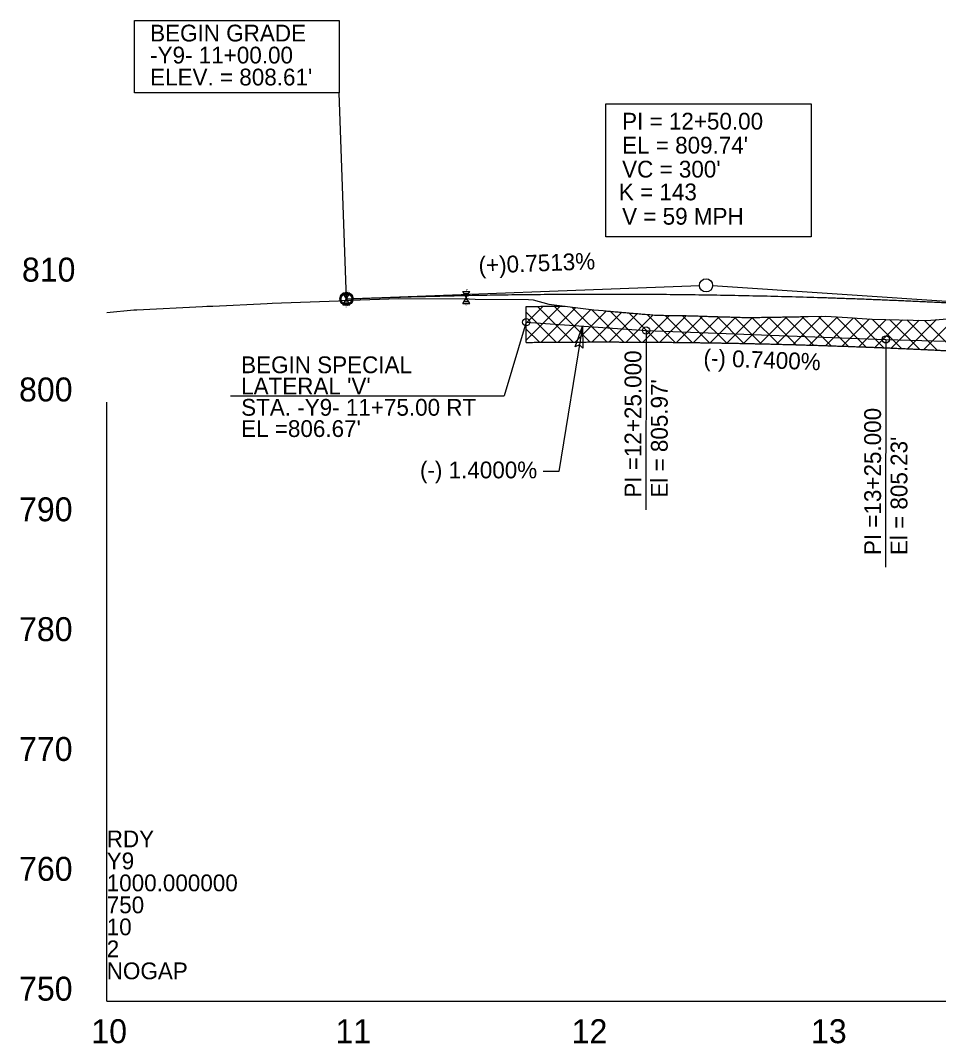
# Model space of a CAD drawing. Extents: x 579185 to 595036, y -53221 to -44640.
# Drawn here: x 591153 to 591536, y -49552.8 to -49125.9 of the extents above; entities that cross this region are included whole.
import ezdxf

# ---------------------------------------------------------------- set-up
doc = ezdxf.new("R2010")
doc.units = 0
for name, color, linetype in [('Exist Profile Cell', 7, 'Continuous'), ('Exist Vertical Profile Ground Line', 7, 'Continuous'), ('Exist Vertical Profile Horizontal Axis Label Major', 7, 'Continuous'), ('Exist Vertical Profile Vertical Axis Label', 7, 'Continuous'), ('Old_Level_2', 7, 'Continuous'), ('Prop Grid Mask', 7, 'Continuous'), ('Prop Hatching', 7, 'Continuous'), ('Prop Terminator CELL', 7, 'Continuous'), ('Prop Vertical Profile Curve Label', 7, 'Continuous'), ('Prop Vertical Profile Ditch Grade Right', 7, 'Continuous'), ('Prop Vertical Profile Ditch Grade Right Label', 7, 'Continuous'), ('Prop Vertical Profile Grade', 7, 'Continuous'), ('Prop Vertical Profile Grade Label', 7, 'Continuous'), ('Prop VPI Ditch Grade Right Label', 7, 'Continuous'), ('Prop VPI Label', 7, 'Continuous')]:
    doc.layers.add(name, color=color, linetype=linetype)

msp = doc.modelspace()

# ---------------------------------------------------------------- linework, layer by layer
at = {"layer": 'Exist Profile Cell'}
for q in [(591188.99, -49285.12), (592048.25, -49535.12), (591188.99, -49535.12)]:
    msp.add_line((591188.99, -49535.12), q, dxfattribs=at)
at = {"layer": 'Exist Vertical Profile Ground Line'}
for points in [[(591188.99, -49247.72), (591200.32, -49246.71), (591201.16, -49246.62), (591201.57, -49246.59), (591228.98, -49245.24), (591230.68, -49245.18), (591233.2, -49245.1), (591255.88, -49243.99), (591258.01, -49243.89), (591285.71, -49242.84), (591286.79, -49242.8), (591310.73, -49241.9), (591340.21, -49242.1), (591342.73, -49242.18), (591364.92, -49242.38), (591366.89, -49242.47), (591373.45, -49244.24), (591392.23, -49246.61), (591396.04, -49246.96), (591396.67, -49247.02), (591397.3, -49247.07), (591397.93, -49247.13), (591398.56, -49247.19), (591399.19, -49247.24), (591399.82, -49247.3), (591400.45, -49247.36), (591401.08, -49247.41), (591401.7, -49247.47), (591402.33, -49247.53), (591402.96, -49247.58), (591403.59, -49247.64), (591404.22, -49247.69), (591404.85, -49247.75), (591405.48, -49247.8), (591406.11, -49247.86), (591406.74, -49247.91), (591407.37, -49247.97), (591408, -49248.02), (591408.63, -49248.07), (591409.25, -49248.13), (591409.88, -49248.18), (591410.51, -49248.23), (591411.14, -49248.29), (591411.77, -49248.34), (591412.4, -49248.39), (591413.03, -49248.44), (591413.66, -49248.49), (591414.29, -49248.55), (591414.92, -49248.6), (591415.55, -49248.65), (591416.18, -49248.7), (591416.8, -49248.75), (591417.43, -49248.8), (591418.06, -49248.85), (591418.69, -49248.88), (591419.32, -49248.89), (591419.95, -49248.91), (591420.58, -49248.92), (591421.21, -49248.93), (591421.84, -49248.94), (591422.47, -49248.95), (591423.1, -49248.96), (591423.73, -49248.97), (591424.35, -49248.98), (591424.98, -49248.99), (591425.61, -49249), (591426.24, -49249.01), (591426.87, -49249.02), (591427.5, -49249.03), (591428.13, -49249.04), (591428.76, -49249.05), (591429.39, -49249.06), (591430.02, -49249.06), (591430.65, -49249.07), (591431.28, -49249.08), (591431.9, -49249.09), (591432.53, -49249.1), (591433.16, -49249.11), (591433.79, -49249.13), (591434.42, -49249.15), (591435.05, -49249.18), (591435.68, -49249.2), (591436.31, -49249.22), (591436.94, -49249.25), (591437.57, -49249.27), (591438.2, -49249.29), (591438.83, -49249.31), (591439.45, -49249.34), (591440.08, -49249.36), (591440.71, -49249.38), (591441.34, -49249.4), (591441.97, -49249.42), (591442.6, -49249.44), (591443.23, -49249.46), (591443.86, -49249.48), (591444.49, -49249.5), (591445.12, -49249.52), (591445.75, -49249.53), (591446.38, -49249.55), (591447, -49249.57), (591447.63, -49249.59)], [(591447.63, -49249.59), (591448.26, -49249.61), (591448.89, -49249.62), (591449.52, -49249.64), (591450.15, -49249.65), (591450.78, -49249.67), (591451.41, -49249.69), (591452.04, -49249.7), (591452.67, -49249.72), (591453.3, -49249.75), (591453.93, -49249.78), (591454.55, -49249.82), (591455.18, -49249.85), (591455.81, -49249.87), (591456.44, -49249.86), (591457.07, -49249.85), (591457.7, -49249.84), (591458.33, -49249.83), (591458.96, -49249.82), (591459.59, -49249.81), (591460.22, -49249.8), (591460.85, -49249.79), (591461.48, -49249.78), (591462.1, -49249.77), (591462.73, -49249.76), (591463.36, -49249.75), (591463.99, -49249.74), (591464.62, -49249.73), (591465.25, -49249.72), (591465.88, -49249.71), (591466.51, -49249.7), (591467.14, -49249.69), (591467.77, -49249.68), (591468.4, -49249.67), (591469.03, -49249.66), (591469.66, -49249.65), (591470.28, -49249.64), (591470.91, -49249.63), (591471.54, -49249.62), (591472.17, -49249.61), (591472.8, -49249.59), (591473.43, -49249.58), (591474.06, -49249.57), (591474.69, -49249.56), (591475.32, -49249.55), (591475.95, -49249.54), (591476.58, -49249.53), (591477.21, -49249.52), (591477.83, -49249.5), (591478.46, -49249.49), (591479.09, -49249.48), (591479.72, -49249.47), (591480.35, -49249.46), (591480.98, -49249.45), (591481.61, -49249.44), (591488.92, -49249.3), (591497.96, -49249.87), (591508.21, -49250.47), (591531.14, -49251.08), (591560.27, -49248.66)]]:
    msp.add_lwpolyline(points, dxfattribs=at)
at = {"layer": 'Old_Level_2'}
for p, q in [((591288.99, -49242.07), (591287.55, -49239.57)), ((591287.55, -49239.57), (591290.43, -49239.57)), ((591288.03, -49240.4), (591289.95, -49240.4)), ((591288.51, -49241.24), (591289.47, -49241.24)), ((591288.99, -49242.07), (591290.43, -49239.57)), ((591338.99, -49241.47), (591337.55, -49238.97)), ((591337.55, -49238.97), (591340.43, -49238.97)), ((591338.03, -49239.8), (591339.95, -49239.8)), ((591338.51, -49240.63), (591339.47, -49240.63)), ((591338.99, -49241.47), (591340.43, -49238.97)), ((591287.55, -49244.57), (591288.99, -49242.07)), ((591287.55, -49244.57), (591290.43, -49244.57)), ((591288.03, -49243.74), (591289.95, -49243.74)), ((591288.51, -49242.91), (591289.47, -49242.91)), ((591290.43, -49244.57), (591288.99, -49242.07)), ((591337.55, -49243.97), (591338.99, -49241.47)), ((591337.55, -49243.97), (591340.43, -49243.97)), ((591338.03, -49243.13), (591339.95, -49243.13)), ((591338.51, -49242.3), (591339.47, -49242.3)), ((591340.43, -49243.97), (591338.99, -49241.47))]:
    msp.add_line(p, q, dxfattribs=at)
at = {"layer": 'Prop Grid Mask'}
for points in [[(591200.54, -49125.91), (591285.94, -49125.91), (591285.94, -49156.1), (591200.54, -49156.1)], [(591397.23, -49160.74), (591482.79, -49160.74), (591482.79, -49216.13), (591397.23, -49216.13)]]:
    msp.add_lwpolyline(points, close=True, dxfattribs=at)
at = {"layer": 'Prop Hatching'}
for p, q in [((591363.99, -49259.31), (591378.19, -49245.11)), ((591363.99, -49252.24), (591371.06, -49245.17)), ((591363.99, -49260.24), (591363.99, -49245.24)), ((591368.65, -49245.19), (591383.54, -49260.08)), ((591375.66, -49245.13), (591390.59, -49260.06)), ((591383.06, -49245.46), (591397.66, -49260.05)), ((591363.99, -49247.6), (591376.51, -49260.12)), ((591370.2, -49260.17), (591384.71, -49245.66)), ((591377.32, -49260.12), (591390.98, -49246.46)), ((591384.43, -49260.08), (591397.43, -49247.09)), ((591391.15, -49246.48), (591404.74, -49260.07)), ((591391.52, -49260.06), (591403.92, -49247.67)), ((591398.6, -49260.05), (591410.43, -49248.23)), ((591398.97, -49247.22), (591411.84, -49260.1)), ((591405.66, -49260.07), (591416.96, -49248.76)), ((591406.73, -49247.91), (591418.96, -49260.14)), ((591412.69, -49260.1), (591423.82, -49248.97)), ((591414.45, -49248.56), (591426.1, -49260.21)), ((591419.72, -49260.15), (591430.79, -49249.07)), ((591421.9, -49248.94), (591433.25, -49260.29)), ((591426.72, -49260.22), (591437.67, -49249.27)), ((591429.08, -49249.05), (591440.43, -49260.4)), ((591433.71, -49260.3), (591444.51, -49249.5)), ((591436.32, -49249.22), (591447.62, -49260.52)), ((591440.68, -49260.4), (591451.39, -49249.69)), ((591443.64, -49249.47), (591454.83, -49260.66)), ((591447.63, -49260.52), (591458.32, -49249.83)), ((591450.92, -49249.67), (591462.06, -49260.82)), ((591454.57, -49260.65), (591465.5, -49249.72)), ((591458.15, -49249.84), (591469.31, -49260.99)), ((591461.49, -49260.8), (591472.7, -49249.6)), ((591465.11, -49249.73), (591476.57, -49261.19)), ((591468.39, -49260.97), (591479.9, -49249.47)), ((591472.06, -49249.61), (591483.86, -49261.4)), ((591475.28, -49261.15), (591487.1, -49249.34)), ((591479.01, -49249.48), (591491.17, -49261.64)), ((591482.15, -49261.35), (591493.89, -49249.61)), ((591485.95, -49249.36), (591498.49, -49261.89)), ((591493.24, -49249.57), (591505.84, -49262.17)), ((591489.01, -49261.57), (591500.56, -49250.02)), ((591495.85, -49261.8), (591507.23, -49250.42)), ((591500.77, -49250.03), (591513.2, -49262.46)), ((591502.67, -49262.05), (591514.09, -49250.63)), ((591508.29, -49250.48), (591520.59, -49262.78)), ((591509.48, -49262.31), (591520.98, -49250.81)), ((591515.55, -49250.67), (591527.99, -49263.11)), ((591516.27, -49262.59), (591527.87, -49250.99)), ((591522.81, -49250.86), (591535.42, -49263.46)), ((591523.05, -49262.88), (591535.19, -49250.74)), ((591529.81, -49263.19), (591542.9, -49250.1)), ((591530.07, -49251.05), (591542.86, -49263.84)), ((591363.99, -49254.67), (591369.5, -49260.18))]:
    msp.add_line(p, q, dxfattribs=at)
for points in [[(591363.99, -49245.24), (591365.01, -49245.23), (591366.02, -49245.22), (591367.04, -49245.21), (591369.04, -49245.19), (591371.03, -49245.17), (591373.03, -49245.15), (591375.03, -49245.13), (591377.02, -49245.12), (591379.02, -49245.11), (591379.43, -49245.11), (591379.84, -49245.1), (591380.24, -49245.1)], [(591363.99, -49260.24), (591365.06, -49260.23), (591366.13, -49260.21), (591367.19, -49260.2), (591369.18, -49260.18), (591371.17, -49260.17), (591373.15, -49260.15), (591375.14, -49260.13), (591377.12, -49260.12), (591379.11, -49260.11), (591381.1, -49260.09), (591383.08, -49260.08), (591385.07, -49260.08), (591387.05, -49260.07), (591389.04, -49260.06), (591391.03, -49260.06), (591393.01, -49260.06), (591395, -49260.05), (591396.98, -49260.05), (591398.97, -49260.05), (591400.96, -49260.06), (591402.94, -49260.06), (591404.93, -49260.07), (591406.91, -49260.07), (591408.9, -49260.08), (591410.89, -49260.09), (591412.87, -49260.1), (591414.86, -49260.11), (591416.84, -49260.13), (591418.83, -49260.14), (591420.82, -49260.16), (591422.8, -49260.18), (591424.79, -49260.2), (591426.77, -49260.22), (591428.76, -49260.24), (591430.75, -49260.26), (591432.73, -49260.29), (591434.72, -49260.31), (591436.71, -49260.34), (591438.69, -49260.37), (591440.68, -49260.4), (591442.66, -49260.43), (591444.65, -49260.47), (591446.64, -49260.5), (591448.62, -49260.54), (591450.61, -49260.57), (591452.59, -49260.61), (591454.58, -49260.65), (591456.57, -49260.69), (591458.55, -49260.74), (591460.54, -49260.78), (591462.52, -49260.83), (591464.51, -49260.87), (591466.5, -49260.92), (591468.48, -49260.97), (591470.47, -49261.02), (591472.45, -49261.08), (591474.44, -49261.13), (591476.43, -49261.18), (591478.41, -49261.24), (591480.4, -49261.3), (591482.38, -49261.36), (591484.37, -49261.42), (591486.36, -49261.48), (591488.34, -49261.55), (591490.33, -49261.61), (591492.31, -49261.68), (591494.3, -49261.75), (591496.29, -49261.81), (591498.27, -49261.89), (591500.26, -49261.96), (591502.24, -49262.03), (591504.23, -49262.11), (591506.22, -49262.18), (591508.2, -49262.26), (591510.19, -49262.34), (591512.17, -49262.42), (591514.16, -49262.5), (591516.15, -49262.58), (591518.13, -49262.67), (591520.12, -49262.75), (591522.1, -49262.84), (591524.09, -49262.93), (591526.08, -49263.02), (591528.06, -49263.11), (591530.05, -49263.21), (591532.03, -49263.3), (591534.02, -49263.4), (591536.01, -49263.49), (591537.99, -49263.59), (591539.98, -49263.69), (591541.96, -49263.79), (591543.95, -49263.89), (591545.94, -49264), (591547.92, -49264.1), (591549.91, -49264.21), (591551.89, -49264.32), (591553.88, -49264.43), (591555.87, -49264.54), (591557.85, -49264.65), (591559.84, -49264.77), (591561.83, -49264.88), (591563.81, -49265), (591565.8, -49265.12), (591567.78, -49265.24), (591569.77, -49265.36), (591571.76, -49265.48), (591573.74, -49265.6), (591575.73, -49265.73), (591577.23, -49265.82), (591578.74, -49265.92), (591580.24, -49266.02)]]:
    msp.add_open_spline(points, degree=3, dxfattribs=at)
at = {"layer": 'Prop Terminator CELL'}
msp.add_lwpolyline([(591384.47, -49262.04), (591387.46, -49253.41), (591387.58, -49262.6), (591386.18, -49261.21)], close=True, dxfattribs=at)
at = {"layer": 'Prop Vertical Profile Curve Label'}
msp.add_line((591288.99, -49242.07), (591285.94, -49156.1), dxfattribs=at)
msp.add_circle((591288.99, -49242.07), 2.25, dxfattribs=at)
at = {"layer": 'Prop Vertical Profile Ditch Grade Right'}
msp.add_line((591363.99, -49251.77), (591413.99, -49255.27), dxfattribs=at)
msp.add_lwpolyline([(591413.99, -49255.27), (591513.99, -49258.97), (591538.99, -49259.77)], dxfattribs=at)
at = {"layer": 'Prop Vertical Profile Ditch Grade Right Label'}
for p, q in [((591363.99, -49251.77), (591354.74, -49282.54)), ((591387.46, -49253.41), (591377.53, -49314.04)), ((591413.99, -49255.27), (591413.92, -49330.07)), ((591513.99, -49258.97), (591513.9, -49354.04)), ((591240.66, -49282.54), (591354.74, -49282.54)), ((591377.53, -49314.04), (591371.09, -49314.04))]:
    msp.add_line(p, q, dxfattribs=at)
at = {"layer": 'Prop Vertical Profile Grade'}
msp.add_spline([(591288.99, -49242.07), (591294.99, -49241.85), (591300.99, -49241.65), (591306.99, -49241.45), (591312.99, -49241.27), (591318.99, -49241.1), (591324.99, -49240.95), (591330.99, -49240.8), (591336.99, -49240.67), (591342.99, -49240.55), (591348.99, -49240.45), (591354.99, -49240.35), (591360.99, -49240.27), (591366.99, -49240.21), (591372.99, -49240.15), (591378.99, -49240.11), (591384.99, -49240.08), (591390.99, -49240.06), (591396.99, -49240.06), (591402.99, -49240.06), (591408.99, -49240.08), (591414.99, -49240.12), (591420.99, -49240.16), (591426.99, -49240.22), (591432.99, -49240.29), (591438.99, -49240.37), (591444.99, -49240.47), (591450.99, -49240.58), (591456.99, -49240.7), (591462.99, -49240.83), (591468.99, -49240.98), (591474.99, -49241.14), (591480.99, -49241.31), (591486.99, -49241.49), (591492.99, -49241.69), (591498.99, -49241.9), (591504.99, -49242.12), (591510.99, -49242.36), (591516.99, -49242.6), (591522.99, -49242.86), (591528.99, -49243.14), (591534.99, -49243.42), (591540.99, -49243.72), (591546.99, -49244.03), (591552.99, -49244.35), (591558.99, -49244.69), (591564.99, -49245.03), (591570.99, -49245.4), (591576.99, -49245.77), (591582.99, -49246.15), (591588.99, -49246.55)], degree=3, dxfattribs=at)
at = {"layer": 'Prop VPI Ditch Grade Right Label'}
for centre in [(591363.99, -49251.77), (591413.99, -49255.27), (591513.99, -49258.97)]:
    msp.add_circle(centre, 1.5, dxfattribs=at)
at = {"layer": 'Prop VPI Label'}
for p, q in [((591288.99, -49242.07), (591436.24, -49236.54)), ((591588.99, -49246.55), (591441.73, -49236.62))]:
    msp.add_line(p, q, dxfattribs=at)
for centre in [(591438.99, -49236.44), (591288.99, -49242.07)]:
    msp.add_circle(centre, 2.75, dxfattribs=at)

# ---------------------------------------------------------------- texts
at = {"layer": 'Exist Profile Cell'}
for s, p in [('RDY', (591188.99, -49470.88)), ('Y9', (591188.99, -49480.06)), ('1000.000000', (591188.99, -49489.23)), ('750', (591188.99, -49498.41)), ('10', (591188.99, -49507.59)), ('2', (591188.99, -49516.76)), ('NOGAP', (591188.99, -49525.94))]:
    msp.add_text(s, height=7, dxfattribs=at).set_placement(p)
at = {"layer": 'Exist Vertical Profile Horizontal Axis Label Major'}
for s, p in [('10', (591182.57, -49552.62)), ('11', (591284.41, -49552.62)), ('12', (591382.96, -49552.62)), ('13', (591482.8, -49552.62))]:
    msp.add_text(s, height=10, dxfattribs=at).set_placement(p)
at = {"layer": 'Exist Vertical Profile Vertical Axis Label'}
for s, p in [('810', (591153.62, -49234.87)), ('800', (591152.42, -49284.87)), ('790', (591152.42, -49334.87)), ('780', (591152.42, -49384.87)), ('770', (591152.42, -49434.87)), ('760', (591152.42, -49484.87)), ('750', (591152.42, -49534.87))]:
    msp.add_text(s, height=10, dxfattribs=at).set_placement(p)
at = {"layer": 'Old_Level_2'}
for p in [(591288.76, -49239.41), (591338.76, -49238.81), (591288.56, -49245.58), (591338.56, -49244.97)]:
    msp.add_text('6"', height=0.8, dxfattribs=at).set_placement(p)
at = {"layer": 'Prop Vertical Profile Curve Label'}
for s, p in [("VC = 300'", (591403.99, -49191.44)), ('K = 143', (591402.64, -49200.95))]:
    msp.add_text(s, height=7, dxfattribs=at).set_placement(p)
at = {"layer": 'Prop Vertical Profile Ditch Grade Right'}
for s, p in [('BEGIN SPECIAL ', (591245.06, -49273.07)), ("LATERAL 'V'", (591245.06, -49281.94)), ('STA. -Y9- 11+75.00 RT ', (591245.06, -49290.82)), ("EL =806.67'", (591245.06, -49299.69))]:
    msp.add_text(s, height=7, dxfattribs=at).set_placement(p)
at = {"layer": 'Prop Vertical Profile Ditch Grade Right Label'}
for s, rotation, p in [('(-) 0.7400%', 357.881, (591437.82, -49270.06)), ('(-) 1.4000%', 360, (591319.66, -49316.95))]:
    msp.add_text(s, height=7, rotation=rotation, dxfattribs=at).set_placement(p)
at = {"layer": 'Prop Vertical Profile Grade Label'}
msp.add_text('(+)0.7513%', height=7, rotation=2.1514, dxfattribs=at).set_placement((591344.23, -49231.55))
at = {"layer": 'Prop VPI Ditch Grade Right Label'}
for s, p in [('PI =12+25.000', (591412.01, -49325)), ("El = 805.97'", (591423.01, -49325)), ('PI =13+25.000', (591511.99, -49348.97)), ("El = 805.23'", (591522.99, -49348.97))]:
    msp.add_text(s, height=7, rotation=90, dxfattribs=at).set_placement(p)
at = {"layer": 'Prop VPI Label'}
for s, p in [('BEGIN GRADE', (591207.1, -49134.67)), ('-Y9- 11+00.00', (591207.1, -49143.85)), ("ELEV. = 808.61'", (591207.1, -49153.02)), ('PI = 12+50.00', (591403.99, -49171.44)), ("EL = 809.74'", (591403.99, -49181.44)), ('V = 59 MPH', (591403.99, -49211.11))]:
    msp.add_text(s, height=7, dxfattribs=at).set_placement(p)

doc.saveas('drawing.dxf')
